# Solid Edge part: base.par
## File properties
Title: Base
Author: Abhinav Rai
Template: Normal.par
Last saved by: Administrator
Revision: 23
Application: Solid Edge
Material: aluminum
Accuracy: 0.990
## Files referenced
..\Asm2.asm
/D:\solid_edge_18\c09_sld_edg_18_030606\Asm2.asm
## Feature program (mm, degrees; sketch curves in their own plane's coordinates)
sketch for "unnamed Protrusion 1" plane through (0, 0, 0) normal (1, 0, 0) x-axis (0, 1, 0)
  line (-34.925, 42.0624) -> (-34.925, -42.0624)
  line (-15.875, -42.0624) -> (-34.925, -42.0624)
  line (-15.875, -42.0624) -> (-15.875, -15.0876)
  line (-15.875, -15.0876) -> (-12.7, -15.0876)
  line (-12.7, -15.0876) -> (-12.7, 0.8001)
  line (-12.7, 0.8001) -> (12.7, 0.8001)
  line (12.7, 0.8001) -> (12.7, -15.0876)
  line (12.7, -15.0876) -> (15.875, -15.0876)
  line (15.875, -15.0876) -> (15.875, -42.0624)
  line (15.875, -42.0624) -> (34.925, -42.0624)
  line (34.925, -42.0624) -> (34.925, 42.0624)
  line (34.925, 42.0624) -> (-34.925, 42.0624)
  dimension (linear) = 15.875
extrude "unnamed Protrusion 1" add finite 184.15 along -normal
sketch for "unnamed Cutout 1" plane through (-92.075, -34.925, 0) normal (0, -1, 0) x-axis (1, 0, 0)
  line (-60.325, 58.9033) -> (-60.325, -2.3876)
  line (-60.325, -2.3876) -> (66.675, -2.3876)
  line (66.675, -2.3876) -> (66.675, 32.5374)
  line (66.675, 32.5374) -> (138.7184, 32.5374)
  line (138.7184, 32.5374) -> (138.7184, 58.9033)
  line (-60.325, 58.9033) -> (138.7184, 58.9033)
extrude "unnamed Cutout 1" cut through along -normal
sketch for "ExtrudedCutout_2" plane through (0, 0, -4.3434) normal (1, 0, 0) x-axis (0, 1, 0)
  line (18.2179, 17.8308) -> (34.925, 17.8308)
  line (42.2755, 17.8308) -> (34.925, 17.8308)
  line (42.2755, 51.2375) -> (42.2755, 17.8308)
  line (-47.5259, 51.2375) -> (42.2755, 51.2375)
  line (-47.5259, 17.8308) -> (-47.5259, 51.2375)
  line (-34.925, 17.8308) -> (-47.5259, 17.8308)
  line (-34.925, 17.8308) -> (-18.2179, 17.8308)
  arc centre (0, 18.6448) radius 18.236 from (-18.2179, 17.8308) to (18.2179, 17.8308) cw
extrude "ExtrudedCutout_2" cut finite 76.2 along -normal
sketch for "Hole_1" plane through (0, 0, -4.7625) normal (1, 0, 0) x-axis (0, 1, 0)
  hole centre (0, 19.0639) bore radius 7.9375
hole "Hole_1" diameter 15.875 through
fillet "Round_2" radius 34.925
sketch for "ExtrudedProtrusion_2" plane through (-92.075, -25.4, -42.0624) normal (0, 0, -1) x-axis (1, 0, 0)
  arc centre (63.5638, -62.2328) radius 28.575 from (92.075, -60.325) to (35.0525, -60.325) cw
  line (35.4, -60.325) -> (92.075, -60.325)
extrude "ExtrudedProtrusion_2" add finite 7.9248 along -normal
sketch for "Hole_2" plane through (-31.5444, 50.1664, -34.1376) normal (0, 0, 1) x-axis (-1, 0, 0)
hole "Hole_2" diameter 7.9248 through
mirror "unnamed Mirror 1" of "ExtrudedProtrusion_2", "Hole_2" about plane through (-92.075, 0, 0) normal (1, 0, 0)
extrude "unnamed Protrusion 2" add finite 7.9248
hole "unnamed Hole 1" through
mirror "unnamed Mirror 2" of "ExtrudedProtrusion_2", "Hole_2", "unnamed Mirror 1" about plane through (0, 0, 0) normal (0, -1, 0)
extrude "unnamed Protrusion 3" add finite 7.9248
hole "unnamed Hole 2" through
extrude "unnamed Protrusion 4" add finite 7.9248
hole "unnamed Hole 3" through
sketch for "Hole_28" plane through (-152.4, 0, 15.5518) normal (1, 0, 0) x-axis (0, 1, 0)
  hole centre (19.05, 7.4606) bore radius 3.175
hole "Hole_28" diameter 6.35 finite
sketch for "unnamed Hole 4" plane through (-152.4, 0, 15.5518) normal (1, 0, 0) x-axis (0, 1, 0)
  hole centre (-19.05, 7.4606) bore radius 3.175
  dimension (linear) = 19.05
  dimension (linear) = 19.05
hole "unnamed Hole 4" finite
pattern "unnamed Pattern 1" of "Hole_28", "unnamed Hole 4"
fillet "Round_24" radius 3.81
hole "Hole_30" diameter 6.35 through
hole "unnamed Hole 5" through
hole "unnamed Hole 6" through
pattern "unnamed Pattern 2" of "Hole_30", "unnamed Hole 5", "unnamed Hole 6"
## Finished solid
Body 1: solid body, 94 faces, 227 edges, 122 vertices.
  Faces by surface: cylinder 41, plane 26, torus 13, blend 12, sphere 2
  Edges by curve: circle 105, line 96, intersection 26
Bounding box of the edges (mm; curved faces can reach further): 184.280 x 130.816 x 84.125, from (-184.2151, -65.4078, -42.0624) to (0.0651, 65.4078, 42.0624).
Cylindrical faces by radius (mm): R3.175 x8, R3.81 x22, R3.9624 x4, R7.9375 x1, R18.236 x1, R28.575 x4, R34.925 x1
Toroidal faces (ring radius, tube radius in mm): R7.62 r3.81 x6, R14.426 r3.81 x1, R24.765 r3.81 x4, R31.115 r3.81 x2
Spherical faces by radius (mm): R3.81 x2
Planar faces by outward normal: +x 4, +y 3, +z 8, -x 2, -y 3, -z 6
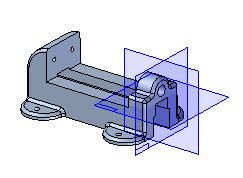
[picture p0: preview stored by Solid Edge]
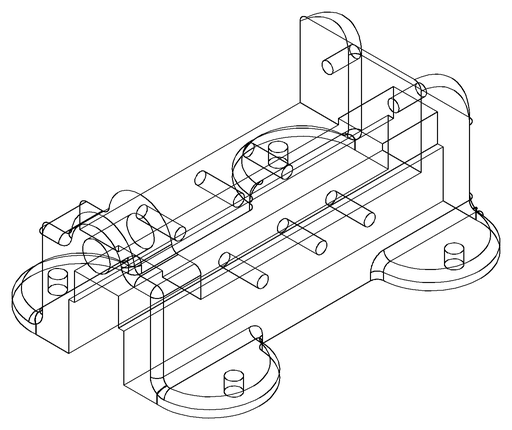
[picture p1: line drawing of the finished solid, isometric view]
